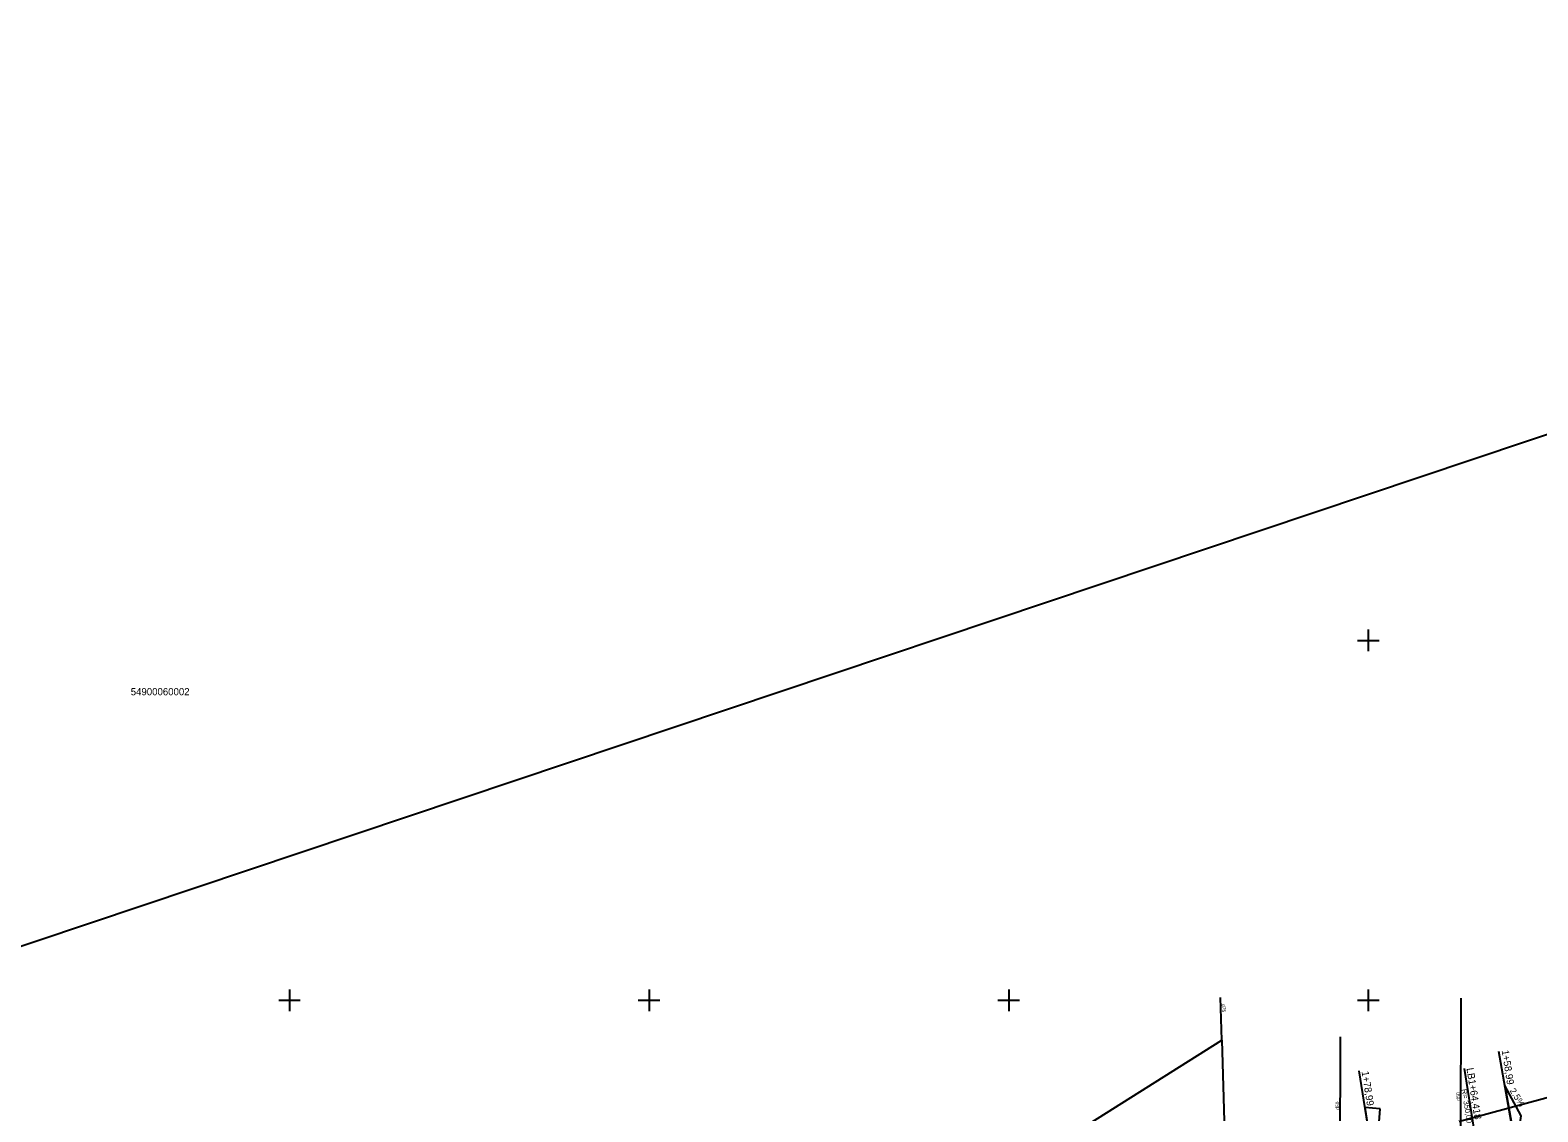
# Model space of a CAD drawing. Extents: x 469981 to 472086, y 246785 to 247785.
# Drawn here: x 471613.9 to 471823.6, y 247634.5 to 247784.8 of the extents above; entities that cross this region are included whole.
import ezdxf

# ---------------------------------------------------------------- set-up
doc = ezdxf.new("R2010")
doc.units = 0
for name, color, linetype in [('0_Virazjas', 7, 'Continuous'), ('5_patagas', 7, 'Continuous'), ('9', 7, 'Continuous'), ('DREN_VADP_####_####_#', 7, 'Continuous'), ('DREN_VADP_####_TKST_#', 7, 'Continuous'), ('DREN_VADP_KLKT_####_#', 7, 'Continuous'), ('DREN_VADP_KLKT_TKST_#', 7, 'Continuous'), ('GEOD_ELEM_####_####_#', 7, 'Continuous'), ('RAMI_PLAN_####_TKST_#', 7, 'Continuous'), ('RAMI_UZMR_####_####_#', 7, 'Continuous'), ('RELJ_NOGA_####_####_#', 7, 'Continuous'), ('RELJ_NOGL_####_####_#', 7, 'Continuous'), ('ROBZ_IERR_####_TKST_#', 7, 'Continuous')]:
    doc.layers.add(name, color=color, linetype=linetype)

msp = doc.modelspace()

# ---------------------------------------------------------------- linework, layer by layer
at = {"layer": '0_Virazjas'}
for p, q in [((471821.89, 247621.63), (471818.17, 247642.87)), ((471798.69, 247640.18), (471802.14, 247618.45))]:
    msp.add_line(p, q, dxfattribs=at)
for points in [[(471820.55, 247629.26), (471821.25, 247633.95), (471819, 247638.13)], [(471801.67, 247634.91), (471799.5, 247635.08), (471800.95, 247625.94)]]:
    msp.add_lwpolyline(points, close=True, dxfattribs=at)
at = {"layer": '5_patagas'}
msp.add_lwpolyline([(471816.54, 247620.74), (471813.4, 247640.49)], dxfattribs=at)
at = {"layer": 'DREN_VADP_####_####_#'}
for points in [[(471812.88, 247631.75), (471812.93, 247650.28)], [(471796.08, 247628.02), (471796.16, 247644.92)], [(471617.26, 247542.22), (471779.63, 247644.43)], [(471779.63, 247644.43), (471780.27, 247622)]]:
    msp.add_lwpolyline(points, dxfattribs=at)
at = {"layer": 'DREN_VADP_KLKT_####_#'}
msp.add_lwpolyline([(471779.63, 247644.43), (471779.46, 247650.37)], dxfattribs=at)
at = {"layer": 'GEOD_ELEM_####_####_#'}
for p, q in [((471800, 247701.5), (471800, 247700)), ((471800, 247701.5), (471800, 247700)), ((471798.5, 247700), (471800, 247700)), ((471798.5, 247700), (471800, 247700)), ((471800, 247700), (471800, 247698.5)), ((471800, 247700), (471801.5, 247700)), ((471800, 247700), (471800, 247698.5)), ((471800, 247700), (471801.5, 247700)), ((471650, 247651.5), (471650, 247650)), ((471700, 247651.5), (471700, 247650)), ((471750, 247651.5), (471750, 247650)), ((471800, 247651.5), (471800, 247650)), ((471648.5, 247650), (471650, 247650)), ((471650, 247650), (471650, 247648.5)), ((471650, 247650), (471651.5, 247650)), ((471698.5, 247650), (471700, 247650)), ((471700, 247650), (471700, 247648.5)), ((471700, 247650), (471701.5, 247650)), ((471748.5, 247650), (471750, 247650)), ((471750, 247650), (471750, 247648.5)), ((471750, 247650), (471751.5, 247650)), ((471798.5, 247650), (471800, 247650)), ((471800, 247650), (471800, 247648.5)), ((471800, 247650), (471801.5, 247650))]:
    msp.add_line(p, q, dxfattribs=at)
at = {"layer": 'RAMI_PLAN_####_TKST_#'}
msp.add_lwpolyline([(472086.15, 247505.1), (471575.09, 247333.79), (471481.34, 247613.5), (471992.39, 247784.8)], close=True, dxfattribs=at)
at = {"layer": 'RAMI_UZMR_####_####_#'}
msp.add_lwpolyline([(471355.9, 247363.1), (471457.4, 247429.3), (471524.25, 247472.9), (471743.7, 247613.61), (471760.56, 247620.64), (471763.72, 247625.03), (471767.05, 247626.61), (471778.29, 247625.91), (471806.56, 247631.53), (471842.31, 247641.2)], dxfattribs=at)
at = {"layer": 'RELJ_NOGA_####_####_#'}
msp.add_spline([(471764.72, 247626.5), (471766.45, 247623.74), (471769.37, 247619.25), (471772.1, 247617.33), (471777.73, 247617.82), (471792.87, 247620.29), (471820.15, 247624.82), (471854.89, 247634.06), (471858.62, 247635.13)], degree=3, dxfattribs=at)
at = {"layer": 'RELJ_NOGL_####_####_#'}
msp.add_spline([(471766.1, 247626.69), (471767.77, 247624.48), (471770.13, 247621.11), (471773.6, 247619.06), (471776.99, 247619.87), (471792.11, 247622.06), (471820.66, 247627.75), (471854.03, 247635.86), (471858.41, 247637.01)], degree=3, dxfattribs=at)

# ---------------------------------------------------------------- texts
msp.add_text('R= 350,00', height=0.75, rotation=279.0079).set_placement((471812.96, 247637.61))
at = {"layer": '0_Virazjas'}
for s, height, rotation, p in [('1+58,99', 1, 279.0079, (471818.55, 247643.01)), ('1+78,99', 1, 279.0079, (471799.07, 247640.07)), ('2.5%', 0.899, 301.9822, (471819.62, 247637.43))]:
    msp.add_text(s, height=height, rotation=rotation, dxfattribs=at).set_placement(p)
at = {"layer": '9'}
msp.add_text('LB1+64,418', height=1, rotation=279.0079, dxfattribs=at).set_placement((471813.65, 247640.53))
at = {"layer": 'DREN_VADP_####_TKST_#'}
for rotation, p in [(89.8362, (471812.74, 247636.05)), (89.7107, (471795.96, 247634.76))]:
    msp.add_text('d50', height=0.5, rotation=rotation, dxfattribs=at).set_placement(p)
at = {"layer": 'DREN_VADP_KLKT_TKST_#'}
msp.add_text('d75', height=0.5, rotation=271.6358, dxfattribs=at).set_placement((471779.63, 247649.48))
at = {"layer": 'ROBZ_IERR_####_TKST_#'}
msp.add_text('54900060002', height=1, dxfattribs=at).set_placement((471627.92, 247692.38))

doc.saveas('drawing.dxf')
